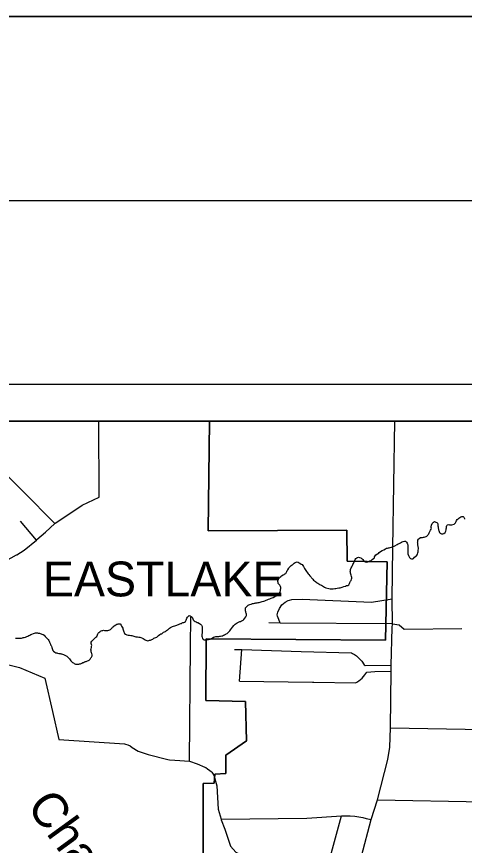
# Model space of a CAD drawing. Extents: x 0 to 44.3, y 0 to 22.
# Drawn here: x 4.381 to 5.6, y 19.746 to 22 of the extents above; entities that cross this region are included whole.
import ezdxf

# ---------------------------------------------------------------- set-up
doc = ezdxf.new("R2010")
doc.units = 0
for name, color, linetype in [('GM_X_City_Street', 7, 'Continuous'), ('GM_X_Corporation', 7, 'Continuous'), ('GM_X_Corporation_Text', 7, 'Continuous'), ('GM_X_County_Road', 7, 'Continuous'), ('GM_X_Major_River_Text', 7, 'Continuous'), ('GM_X_Minor_River', 7, 'Continuous'), ('SH_Border', 7, 'Continuous'), ('SH_Cut_Line', 7, 'Continuous'), ('SH_Data', 7, 'Continuous')]:
    doc.layers.add(name, color=color, linetype=linetype)

msp = doc.modelspace()

# ---------------------------------------------------------------- linework, layer by layer
at = {"layer": 'GM_X_City_Street'}
for p, q in [((4.6058, 20.6926), (4.6052, 20.9)), ((4.4353, 20.5762), (4.3918, 20.6277)), ((4.9885, 20.1926), (4.9948, 20.2785)), ((5.3993, 20.0658), (5.9204, 20.0559)), ((5.3638, 19.8701), (5.8967, 19.8594))]:
    msp.add_line(p, q, dxfattribs=at)
for points in [[(4.4852, 20.6211), (4.2264, 20.8819), (4.1804, 20.8984), (4.1789, 20.9)], [(4.1336, 20.414), (4.1983, 20.4481), (4.3144, 20.4991), (4.3813, 20.5358), (4.3819, 20.5361), (4.4017, 20.5489), (4.4353, 20.5762), (4.4368, 20.5775), (4.4602, 20.5979), (4.4852, 20.6211), (4.4861, 20.622), (4.5074, 20.6361), (4.5604, 20.671), (4.6058, 20.6926)], [(5.0992, 20.3504), (5.0949, 20.3598), (5.0918, 20.3693), (5.0911, 20.373), (5.0921, 20.3799), (5.0974, 20.3902), (5.1038, 20.3997), (5.1128, 20.4074), (5.1206, 20.4117), (5.1246, 20.4129), (5.1302, 20.4143), (5.1589, 20.4154), (5.3477, 20.4075), (5.404, 20.4161)], [(4.8517, 19.9752), (4.8548, 20.2864), (4.8556, 20.3668)], [(5.4045, 20.3486), (5.0992, 20.3504), (5.0681, 20.351)], [(5.4045, 20.3486), (5.4228, 20.3453), (5.4365, 20.334), (5.5929, 20.3356)], [(4.9749, 20.2789), (4.9948, 20.2785), (5.1558, 20.2735), (5.2927, 20.2692), (5.2957, 20.268), (5.3012, 20.2652), (5.3069, 20.2609), (5.3212, 20.2467), (5.3275, 20.2368), (5.3304, 20.2346), (5.4011, 20.2355)], [(5.1909, 20.1894), (5.3039, 20.1876), (5.3077, 20.1895), (5.3132, 20.1935), (5.3218, 20.2009), (5.3296, 20.2098), (5.3345, 20.2165), (5.3561, 20.2187), (5.4011, 20.2196)], [(4.9885, 20.1926), (5.1869, 20.1895), (5.1909, 20.1894)], [(4.938, 19.8173), (5.1714, 19.8194), (5.2659, 19.8265), (5.2896, 19.826), (5.3022, 19.8252), (5.3128, 19.8237), (5.3241, 19.8214), (5.3329, 19.8188), (5.3468, 19.816)], [(5.1712, 19.5146), (5.2296, 19.6928), (5.2414, 19.7366), (5.2659, 19.8265)]]:
    msp.add_lwpolyline(points, dxfattribs=at)
at = {"layer": 'GM_X_Corporation'}
for points in [[(4.8885, 19.4219), (4.8897, 19.914), (4.9196, 19.9147), (4.9212, 19.9392), (4.9507, 19.9415), (4.9514, 19.9913), (5.0073, 20.0297), (5.0045, 20.1371), (4.8961, 20.1397), (4.8974, 20.3076), (5.3854, 20.3035), (5.3905, 20.517), (5.2813, 20.5184), (5.28, 20.6031), (4.9031, 20.6013), (4.9066, 20.9), (3.5534, 20.9)], [(8.9, 20.9), (3.6041, 20.9)], [(8.9, 20.9), (3.6041, 20.9)], [(5.9378, 20.9), (4.9066, 20.9), (4.9031, 20.6013), (5.28, 20.6031), (5.2813, 20.5184), (5.3905, 20.517), (5.3854, 20.3035), (4.8974, 20.3076), (4.8961, 20.1397), (5.0045, 20.1371), (5.0073, 20.0297), (4.9514, 19.9913), (4.9507, 19.9415), (4.9212, 19.9392), (4.9196, 19.9147), (4.8897, 19.914), (4.8885, 19.4219)]]:
    msp.add_lwpolyline(points, dxfattribs=at)
at = {"layer": 'GM_X_County_Road'}
for points in [[(5.4041, 20.3373), (5.4045, 20.3486), (5.404, 20.4161), (5.4059, 20.5555), (5.4108, 20.9)], [(5.2657, 19.5144), (5.2755, 19.5505), (5.3203, 19.716), (5.3468, 19.816), (5.3638, 19.8701), (5.3916, 19.979), (5.3973, 20.0125), (5.3993, 20.0658), (5.4011, 20.2196), (5.4011, 20.2355), (5.4041, 20.3373)], [(4.3565, 20.2375), (4.3892, 20.2298), (4.4588, 20.2007), (4.4795, 20.11), (4.4969, 20.034), (4.6753, 20.0222), (4.6783, 20.0213), (4.6842, 20.0191), (4.6903, 20.0163), (4.6963, 20.0124), (4.7128, 20.0017), (4.7399, 19.9927), (4.7932, 19.9795), (4.7978, 19.9783), (4.8118, 19.9775)], [(4.8118, 19.9775), (4.8517, 19.9752), (4.8727, 19.968), (4.8937, 19.9588), (4.8968, 19.9574), (4.9013, 19.9542), (4.9074, 19.9492), (4.911, 19.9465)], [(4.911, 19.9465), (4.9128, 19.9451), (4.9181, 19.937), (4.9266, 19.9075), (4.9301, 19.8445), (4.938, 19.8173), (4.9386, 19.8151), (4.9482, 19.7895), (4.964, 19.7435), (4.9785, 19.7276), (4.9893, 19.7218), (5.011, 19.7138), (5.0349, 19.6986), (5.0515, 19.6849), (5.0689, 19.6603), (5.0942, 19.6161), (5.1014, 19.5937), (5.1188, 19.5597), (5.1383, 19.5351), (5.1513, 19.5228), (5.1712, 19.5146), (5.2608, 19.4963)]]:
    msp.add_lwpolyline(points, dxfattribs=at)
at = {"layer": 'GM_X_Minor_River'}
for points in [[(5.4889, 20.584), (5.4912, 20.5845), (5.4938, 20.5852), (5.4961, 20.586), (5.498, 20.5868), (5.5006, 20.5891), (5.5021, 20.591), (5.5032, 20.5933), (5.5043, 20.5956), (5.5058, 20.5991), (5.5077, 20.6029), (5.5095, 20.6056), (5.5107, 20.6075), (5.5102, 20.6105), (5.5102, 20.6124), (5.5106, 20.617), (5.5128, 20.6208), (5.5158, 20.625), (5.5188, 20.6266), (5.5222, 20.6251), (5.5249, 20.6244), (5.5268, 20.6217), (5.5276, 20.6198), (5.528, 20.6168), (5.5284, 20.6149), (5.5288, 20.6126), (5.5292, 20.6107), (5.5301, 20.6039), (5.5305, 20.602), (5.5312, 20.5993), (5.5324, 20.5967), (5.5343, 20.5952), (5.5362, 20.594), (5.5381, 20.5933), (5.54, 20.5929), (5.5419, 20.5929), (5.5442, 20.5937), (5.5476, 20.5964), (5.5491, 20.5983), (5.5498, 20.6006), (5.5506, 20.6041), (5.5505, 20.6067), (5.5513, 20.6094), (5.5516, 20.6113), (5.552, 20.6132), (5.5527, 20.6155), (5.5542, 20.6178), (5.5576, 20.6182), (5.5599, 20.6179), (5.5618, 20.6175), (5.5637, 20.6175), (5.5663, 20.6172), (5.5728, 20.6195), (5.5739, 20.6214), (5.5758, 20.6233), (5.5776, 20.6264), (5.5791, 20.6291), (5.581, 20.6321), (5.5829, 20.6337), (5.5855, 20.6356), (5.5878, 20.6375), (5.5904, 20.6395), (5.593, 20.6403), (5.5965, 20.6403), (5.5988, 20.6384), (5.6003, 20.635), (5.6007, 20.6327)], [(5.2939, 20.5037), (5.2954, 20.5068), (5.2969, 20.5095), (5.2984, 20.5125), (5.2991, 20.5144), (5.3003, 20.5171), (5.3017, 20.5202), (5.3032, 20.5236), (5.3051, 20.5259), (5.3073, 20.5282), (5.3092, 20.529), (5.3123, 20.5294), (5.3149, 20.5291), (5.318, 20.5276), (5.3199, 20.5264), (5.3218, 20.5249), (5.3237, 20.5234), (5.326, 20.5204), (5.3283, 20.5178), (5.3302, 20.5167), (5.3329, 20.5163), (5.3356, 20.5167), (5.3375, 20.5171), (5.3397, 20.5179), (5.3431, 20.5194), (5.3461, 20.521), (5.3491, 20.5237), (5.3529, 20.5256), (5.3555, 20.5279), (5.3555, 20.531), (5.3596, 20.5356), (5.3638, 20.5387), (5.3664, 20.5395), (5.3683, 20.5421), (5.3721, 20.5448), (5.3766, 20.5476), (5.3811, 20.5499), (5.3853, 20.5522), (5.3887, 20.5538), (5.3913, 20.5545), (5.3936, 20.5549), (5.3955, 20.5553), (5.3981, 20.5561), (5.4015, 20.5569), (5.4068, 20.5585), (5.4087, 20.5593), (5.411, 20.5608), (5.4174, 20.5643), (5.4204, 20.5655), (5.4223, 20.5666), (5.4242, 20.5678), (5.4264, 20.569), (5.4287, 20.5701), (5.4306, 20.5713), (5.4336, 20.5725), (5.437, 20.5733), (5.4401, 20.5733), (5.4428, 20.5707), (5.4443, 20.5676), (5.4451, 20.5654), (5.4459, 20.5631), (5.446, 20.5543), (5.446, 20.5517), (5.446, 20.5486), (5.4461, 20.546), (5.4465, 20.5425), (5.4465, 20.5391), (5.4477, 20.5346), (5.4489, 20.5323), (5.45, 20.5304), (5.4512, 20.5285), (5.4535, 20.5262), (5.4565, 20.5251), (5.46, 20.5255), (5.4619, 20.5259), (5.4648, 20.5298), (5.4682, 20.5325), (5.4701, 20.5336), (5.4716, 20.5363), (5.4727, 20.5382), (5.4734, 20.5413), (5.4742, 20.5443), (5.4749, 20.5466), (5.4749, 20.5489), (5.4752, 20.5527), (5.4752, 20.5554), (5.4748, 20.5573), (5.4744, 20.5592), (5.474, 20.5614), (5.4732, 20.5637), (5.4732, 20.5664), (5.4728, 20.5683), (5.4731, 20.5702), (5.4731, 20.5729), (5.4738, 20.5759), (5.4753, 20.5782), (5.4772, 20.5801), (5.4806, 20.5828), (5.484, 20.5832), (5.4859, 20.5836), (5.4889, 20.584)], [(5.0999, 20.4417), (5.1003, 20.4444), (5.1006, 20.447), (5.0998, 20.4501), (5.0979, 20.4535), (5.0952, 20.4565), (5.0937, 20.4584), (5.0933, 20.4607), (5.0925, 20.4637), (5.0928, 20.4679), (5.0943, 20.4706), (5.0958, 20.4729), (5.0969, 20.4748), (5.1003, 20.4775), (5.1029, 20.479), (5.1071, 20.4817), (5.1093, 20.4829), (5.1116, 20.4844), (5.1139, 20.4856), (5.1157, 20.4887), (5.1168, 20.4906), (5.1183, 20.4933), (5.1194, 20.4956), (5.1221, 20.4994), (5.1236, 20.5013), (5.125, 20.5032), (5.1269, 20.5051), (5.1288, 20.5071), (5.1311, 20.5086), (5.1329, 20.5101), (5.1348, 20.5117), (5.1371, 20.5132), (5.1393, 20.5148), (5.142, 20.5159), (5.145, 20.5167), (5.1481, 20.516), (5.1504, 20.5145), (5.1526, 20.513), (5.1561, 20.5108), (5.1584, 20.5093), (5.1603, 20.507), (5.1622, 20.504), (5.1634, 20.5021), (5.1653, 20.4991), (5.1673, 20.496), (5.1684, 20.4934), (5.1704, 20.4903), (5.1731, 20.4873), (5.1754, 20.4843), (5.1769, 20.4824), (5.18, 20.4786), (5.1831, 20.4753), (5.1842, 20.4734), (5.1858, 20.4715), (5.1877, 20.4696), (5.19, 20.4673), (5.1923, 20.4654), (5.1946, 20.4636), (5.1969, 20.4617), (5.1992, 20.4602), (5.2011, 20.4587), (5.2038, 20.4572), (5.2061, 20.4557), (5.2083, 20.4546), (5.211, 20.4531), (5.2137, 20.4516), (5.2164, 20.4501), (5.2198, 20.4482), (5.2229, 20.4467), (5.2312, 20.4445), (5.2354, 20.4438), (5.2392, 20.4438), (5.2434, 20.4439), (5.2472, 20.4443), (5.2506, 20.4443), (5.254, 20.4451), (5.2582, 20.4459), (5.2623, 20.4467), (5.2672, 20.4483), (5.2722, 20.4495), (5.2763, 20.4507), (5.2797, 20.4522), (5.2831, 20.453), (5.2854, 20.4546), (5.2873, 20.458), (5.2887, 20.4611), (5.2902, 20.4645), (5.2921, 20.4661), (5.2932, 20.4695), (5.2935, 20.4722), (5.2935, 20.4744), (5.2927, 20.4775), (5.2919, 20.4805), (5.2915, 20.4832), (5.2907, 20.4858), (5.2899, 20.4885), (5.2895, 20.4911), (5.2899, 20.4938), (5.2906, 20.4965), (5.2917, 20.5007), (5.2939, 20.5037)], [(4.8867, 20.3369), (4.8867, 20.3342), (4.8867, 20.3319), (4.8864, 20.3266), (4.8864, 20.3243), (4.8864, 20.3224), (4.8861, 20.3205), (4.8861, 20.3171), (4.8861, 20.3152), (4.8866, 20.3122), (4.8877, 20.3087), (4.8893, 20.3065), (4.8916, 20.305), (4.895, 20.3046), (4.8992, 20.305), (4.9018, 20.3055), (4.9041, 20.3059), (4.906, 20.3063), (4.9082, 20.307), (4.9116, 20.3082), (4.9139, 20.3098), (4.9173, 20.3121), (4.9207, 20.3132), (4.9237, 20.314), (4.9271, 20.3141), (4.9302, 20.3141), (4.9321, 20.3141), (4.9343, 20.3145), (4.9366, 20.3149), (4.9397, 20.3153), (4.9415, 20.3161), (4.9449, 20.3173), (4.9472, 20.3188), (4.9498, 20.32), (4.9548, 20.3223), (4.9566, 20.3239), (4.9589, 20.3266), (4.9615, 20.3289), (4.9641, 20.3323), (4.966, 20.3354), (4.969, 20.3396), (4.9727, 20.3442), (4.9765, 20.3473), (4.9791, 20.3492), (4.9814, 20.3508), (4.984, 20.3523), (4.987, 20.3539), (4.9893, 20.3546), (4.9912, 20.355), (4.9935, 20.3562), (4.9961, 20.3577), (4.998, 20.3585), (5.0003, 20.3601), (5.0029, 20.3635), (5.0055, 20.367), (5.0066, 20.3689), (5.0074, 20.3708), (5.0069, 20.375), (5.0061, 20.3772), (5.0057, 20.3791), (5.005, 20.381), (5.0042, 20.3833), (5.0041, 20.3875), (5.0041, 20.3894), (5.0048, 20.3921), (5.0116, 20.399), (5.0135, 20.3998), (5.0161, 20.4009), (5.0195, 20.4021), (5.0214, 20.4029), (5.0237, 20.4037), (5.0267, 20.4041), (5.0286, 20.4045), (5.0309, 20.4049), (5.0328, 20.4053), (5.0366, 20.4057), (5.0392, 20.4061), (5.0419, 20.4065), (5.0441, 20.4073), (5.0468, 20.4081), (5.0502, 20.4093), (5.054, 20.4101), (5.057, 20.4112), (5.0608, 20.4124), (5.0638, 20.4136), (5.0668, 20.4151), (5.0706, 20.4167), (5.074, 20.4179), (5.077, 20.419), (5.0797, 20.4202), (5.0823, 20.4214), (5.0846, 20.4222), (5.0865, 20.4233), (5.0884, 20.4241), (5.091, 20.4264), (5.0929, 20.4283), (5.0947, 20.4299), (5.0974, 20.4322), (5.0985, 20.4348), (5.1, 20.439), (5.0999, 20.4417)], [(4.6448, 20.341), (4.6475, 20.3433), (4.6512, 20.346), (4.6542, 20.3475), (4.6561, 20.3479), (4.6584, 20.3483), (4.6603, 20.3487), (4.663, 20.3484), (4.6657, 20.3446), (4.6668, 20.342), (4.6688, 20.3393), (4.6707, 20.3363), (4.6711, 20.3344), (4.6715, 20.3317), (4.6723, 20.3291), (4.6731, 20.3268), (4.6739, 20.3245), (4.675, 20.3222), (4.6777, 20.32), (4.6796, 20.3192), (4.6819, 20.3181), (4.6849, 20.3178), (4.6887, 20.3171), (4.6922, 20.3167), (4.6948, 20.3164), (4.6975, 20.3156), (4.7005, 20.3145), (4.7036, 20.3138), (4.7059, 20.3134), (4.7081, 20.3127), (4.7104, 20.3127), (4.7138, 20.312), (4.7169, 20.312), (4.7199, 20.3113), (4.7241, 20.3098), (4.726, 20.3087), (4.7287, 20.3068), (4.7318, 20.3049), (4.7337, 20.3038), (4.7356, 20.3031), (4.7386, 20.3023), (4.7417, 20.3027), (4.7436, 20.3035), (4.7458, 20.3043), (4.7481, 20.3051), (4.75, 20.3059), (4.7522, 20.307), (4.7549, 20.309), (4.7579, 20.3105), (4.7605, 20.3113), (4.7628, 20.3121), (4.7677, 20.3163), (4.7715, 20.3194), (4.7745, 20.3209), (4.7764, 20.3213), (4.7809, 20.326), (4.7865, 20.3279), (4.7892, 20.3306), (4.7918, 20.3321), (4.7937, 20.3333), (4.7975, 20.3368), (4.8005, 20.3387), (4.8024, 20.3395), (4.8054, 20.341), (4.8084, 20.3418), (4.8122, 20.343), (4.8148, 20.3438), (4.8175, 20.3446), (4.8197, 20.3457), (4.8224, 20.3469), (4.8254, 20.3481), (4.8281, 20.3492), (4.8303, 20.3496), (4.8322, 20.3508), (4.8341, 20.3516), (4.8364, 20.3524), (4.8383, 20.3531), (4.8409, 20.3547), (4.8428, 20.3585), (4.8442, 20.3612), (4.845, 20.3639), (4.8465, 20.3665), (4.8491, 20.3696), (4.851, 20.3708), (4.854, 20.3697), (4.8563, 20.3685), (4.859, 20.3667), (4.8605, 20.3644), (4.8613, 20.3621), (4.8625, 20.3595), (4.8644, 20.3568), (4.8671, 20.355), (4.8698, 20.3535), (4.8721, 20.3523), (4.8751, 20.3516), (4.8793, 20.3494), (4.8824, 20.3471), (4.885, 20.3445), (4.8862, 20.3414), (4.8862, 20.3395), (4.8867, 20.3369)], [(4.4626, 20.3107), (4.4657, 20.308), (4.4672, 20.3054), (4.4691, 20.3027), (4.4699, 20.3008), (4.4707, 20.2989), (4.4719, 20.297), (4.4726, 20.2952), (4.4734, 20.2933), (4.4742, 20.2914), (4.4754, 20.2891), (4.4761, 20.2872), (4.4773, 20.2842), (4.4781, 20.2811), (4.4793, 20.2781), (4.4804, 20.2754), (4.4816, 20.2736), (4.4854, 20.2709), (4.4881, 20.2698), (4.4908, 20.2695), (4.4927, 20.2687), (4.4965, 20.268), (4.4984, 20.2676), (4.5003, 20.2673), (4.5022, 20.2669), (4.5041, 20.2665), (4.5067, 20.2658), (4.509, 20.2651), (4.5113, 20.2643), (4.5148, 20.2625), (4.5182, 20.2606), (4.5201, 20.2587), (4.5224, 20.2557), (4.5251, 20.2531), (4.527, 20.2504), (4.529, 20.2481), (4.532, 20.2451), (4.5339, 20.2436), (4.5362, 20.2421), (4.5385, 20.2406), (4.542, 20.2391), (4.5439, 20.2388), (4.5511, 20.2388), (4.553, 20.2392), (4.5556, 20.24), (4.5575, 20.2408), (4.5594, 20.2416), (4.5617, 20.2428), (4.5639, 20.2435), (4.5666, 20.2447), (4.5692, 20.2455), (4.5711, 20.2459), (4.5745, 20.2478), (4.5768, 20.249), (4.5787, 20.2498), (4.5817, 20.2521), (4.5839, 20.2555), (4.5854, 20.2574), (4.5865, 20.2594), (4.5876, 20.2617), (4.5869, 20.2639), (4.5861, 20.2673), (4.5853, 20.2692), (4.5845, 20.2719), (4.5841, 20.2753), (4.584, 20.278), (4.5848, 20.2807), (4.5851, 20.2837), (4.5855, 20.2856), (4.5858, 20.2875), (4.5862, 20.2894), (4.585, 20.2924), (4.5842, 20.2947), (4.5849, 20.2985), (4.5864, 20.3012), (4.5917, 20.3066), (4.5939, 20.3089), (4.5973, 20.312), (4.5996, 20.3143), (4.6014, 20.3181), (4.6025, 20.3208), (4.6037, 20.3231), (4.6051, 20.325), (4.6078, 20.3269), (4.6097, 20.3285), (4.6119, 20.3296), (4.6142, 20.33), (4.6161, 20.3304), (4.618, 20.3308), (4.621, 20.3305), (4.6237, 20.3301), (4.6256, 20.3298), (4.6275, 20.3298), (4.6298, 20.3302), (4.6324, 20.331), (4.6351, 20.3321), (4.6369, 20.3333), (4.6388, 20.3344), (4.6414, 20.3371), (4.6429, 20.3394), (4.6448, 20.341)], [(4.3787, 20.3091), (4.3818, 20.3091), (4.3856, 20.3091), (4.3894, 20.3092), (4.3928, 20.3096), (4.395, 20.3096), (4.3977, 20.31), (4.3996, 20.3108), (4.4019, 20.3112), (4.406, 20.3124), (4.4098, 20.3136), (4.4124, 20.3151), (4.4151, 20.3163), (4.4177, 20.3178), (4.4207, 20.3194), (4.4226, 20.3202), (4.4279, 20.3221), (4.4306, 20.3233), (4.4332, 20.3237), (4.4359, 20.3237), (4.4382, 20.3237), (4.4401, 20.3234), (4.442, 20.323), (4.4439, 20.3226), (4.4461, 20.3219), (4.4484, 20.3212), (4.4503, 20.3204), (4.4538, 20.3189), (4.4561, 20.3171), (4.4591, 20.314), (4.4607, 20.3122), (4.4626, 20.3107)]]:
    msp.add_lwpolyline(points, dxfattribs=at)
at = {"layer": 'SH_Border'}
msp.add_lwpolyline([(1.5, 21.5), (33.5, 21.5), (33.5, 0.5), (1.5, 0.5)], close=True, dxfattribs=at)
at = {"layer": 'SH_Cut_Line'}
for points in [[(0, 0), (34, 0), (34, 22), (0, 22)], [(0, 22), (34, 22), (34, 0), (0, 0)]]:
    msp.add_lwpolyline(points, close=True, dxfattribs=at)
at = {"layer": 'SH_Data'}
for p, q in [((2, 21), (9, 21)), ((2.1, 20.9), (8.9, 20.9)), ((2.1, 20.9), (8.9, 20.9))]:
    msp.add_line(p, q, dxfattribs=at)

# ---------------------------------------------------------------- texts
at = {"layer": 'GM_X_Corporation_Text'}
msp.add_text('EASTLAKE', height=0.0947, rotation=0, dxfattribs=at).set_placement((4.4532, 20.423))
at = {"layer": 'GM_X_Major_River_Text'}
msp.add_text('Chagrin', height=0.09477, rotation=305.9502, dxfattribs=at).set_placement((4.4069, 19.8523))

doc.saveas('drawing.dxf')
